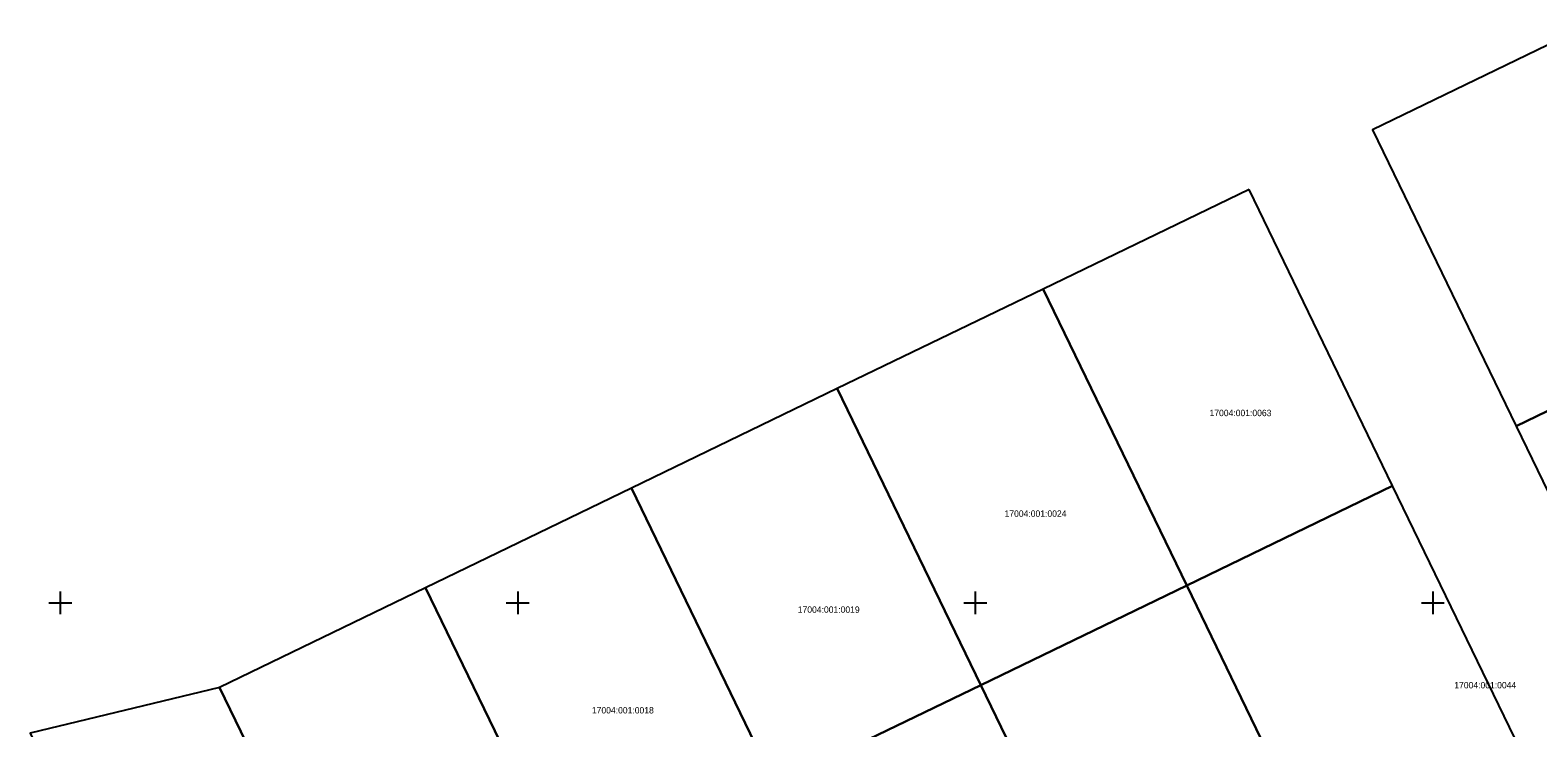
# Model space of a CAD drawing. Extents: x 643307 to 644029, y 6457938 to 6458417.
# Drawn here: x 643496.7 to 643661.5, y 6458286.3 to 6458362.6 of the extents above; entities that cross this region are included whole.
import ezdxf

# ---------------------------------------------------------------- set-up
doc = ezdxf.new("R2010")
doc.units = 0
for name, color, linetype in [('30_TEE', 7, 'Continuous'), ('40_PIIR', 7, 'Continuous'), ('63_VORK', 7, 'Continuous'), ('Default', 7, 'Continuous')]:
    doc.layers.add(name, color=color, linetype=linetype)

# ---------------------------------------------------------------- blocks, each defined once
blk = doc.blocks.new('VKORIS')
at = {"layer": '30_TEE'}
for p, q in [((-2.5, 0), (2.5, 0)), ((0, 2.5), (0, -2.5))]:
    blk.add_line(p, q, dxfattribs=at)

msp = doc.modelspace()

# ---------------------------------------------------------------- linework, layer by layer
at = {"layer": '40_PIIR'}
for points in [[(643665.93, 6458362.61), (643643.43, 6458351.73), (643659.11, 6458319.33), (643681.62, 6458330.21)], [(643629.93, 6458345.2), (643607.42, 6458334.31), (643623.11, 6458301.91), (643645.61, 6458312.8)], [(643607.42, 6458334.31), (643584.92, 6458323.42), (643600.6, 6458291.02), (643623.11, 6458301.91)], [(643674.8, 6458286.93), (643697.3, 6458297.82), (643681.62, 6458330.21), (643659.11, 6458319.33)], [(643584.92, 6458323.42), (643562.42, 6458312.54), (643578.1, 6458280.14), (643600.6, 6458291.02)], [(643638.79, 6458269.51), (643661.29, 6458280.4), (643645.61, 6458312.8), (643623.11, 6458301.91)], [(643562.42, 6458312.54), (643539.91, 6458301.65), (643555.6, 6458269.25), (643578.1, 6458280.14)], [(643539.91, 6458301.65), (643517.41, 6458290.76), (643533.09, 6458258.36), (643555.6, 6458269.25)], [(643616.29, 6458258.63), (643638.79, 6458269.51), (643623.11, 6458301.91), (643600.6, 6458291.02)], [(643517.41, 6458290.76), (643496.71, 6458285.74), (643512.36, 6458253.09), (643533.09, 6458258.36)], [(643593.78, 6458247.74), (643616.29, 6458258.63), (643600.6, 6458291.02), (643578.1, 6458280.14)]]:
    msp.add_lwpolyline(points, close=True, dxfattribs=at)

# ---------------------------------------------------------------- block references
at = {"layer": '63_VORK', "xscale": 0.5, "yscale": 0.5}
for p in [(643500, 6458300), (643550, 6458300), (643600, 6458300), (643650, 6458300)]:
    msp.add_blockref('VKORIS', p, dxfattribs=at)

# ---------------------------------------------------------------- texts
at = {"layer": '40_PIIR'}
for s, p in [('17004:001:0063', (643625.6, 6458320.41)), ('17004:001:0024', (643603.2, 6458309.41)), ('17004:001:0019', (643580.6, 6458298.91)), ('17004:001:0018', (643558.1, 6458287.91))]:
    msp.add_text(s, height=0.7, dxfattribs=at).set_placement(p)
at = {"layer": 'Default'}
msp.add_text('17004:001:0044', height=0.7, dxfattribs=at).set_placement((643652.35, 6458290.65))

doc.saveas('drawing.dxf')
